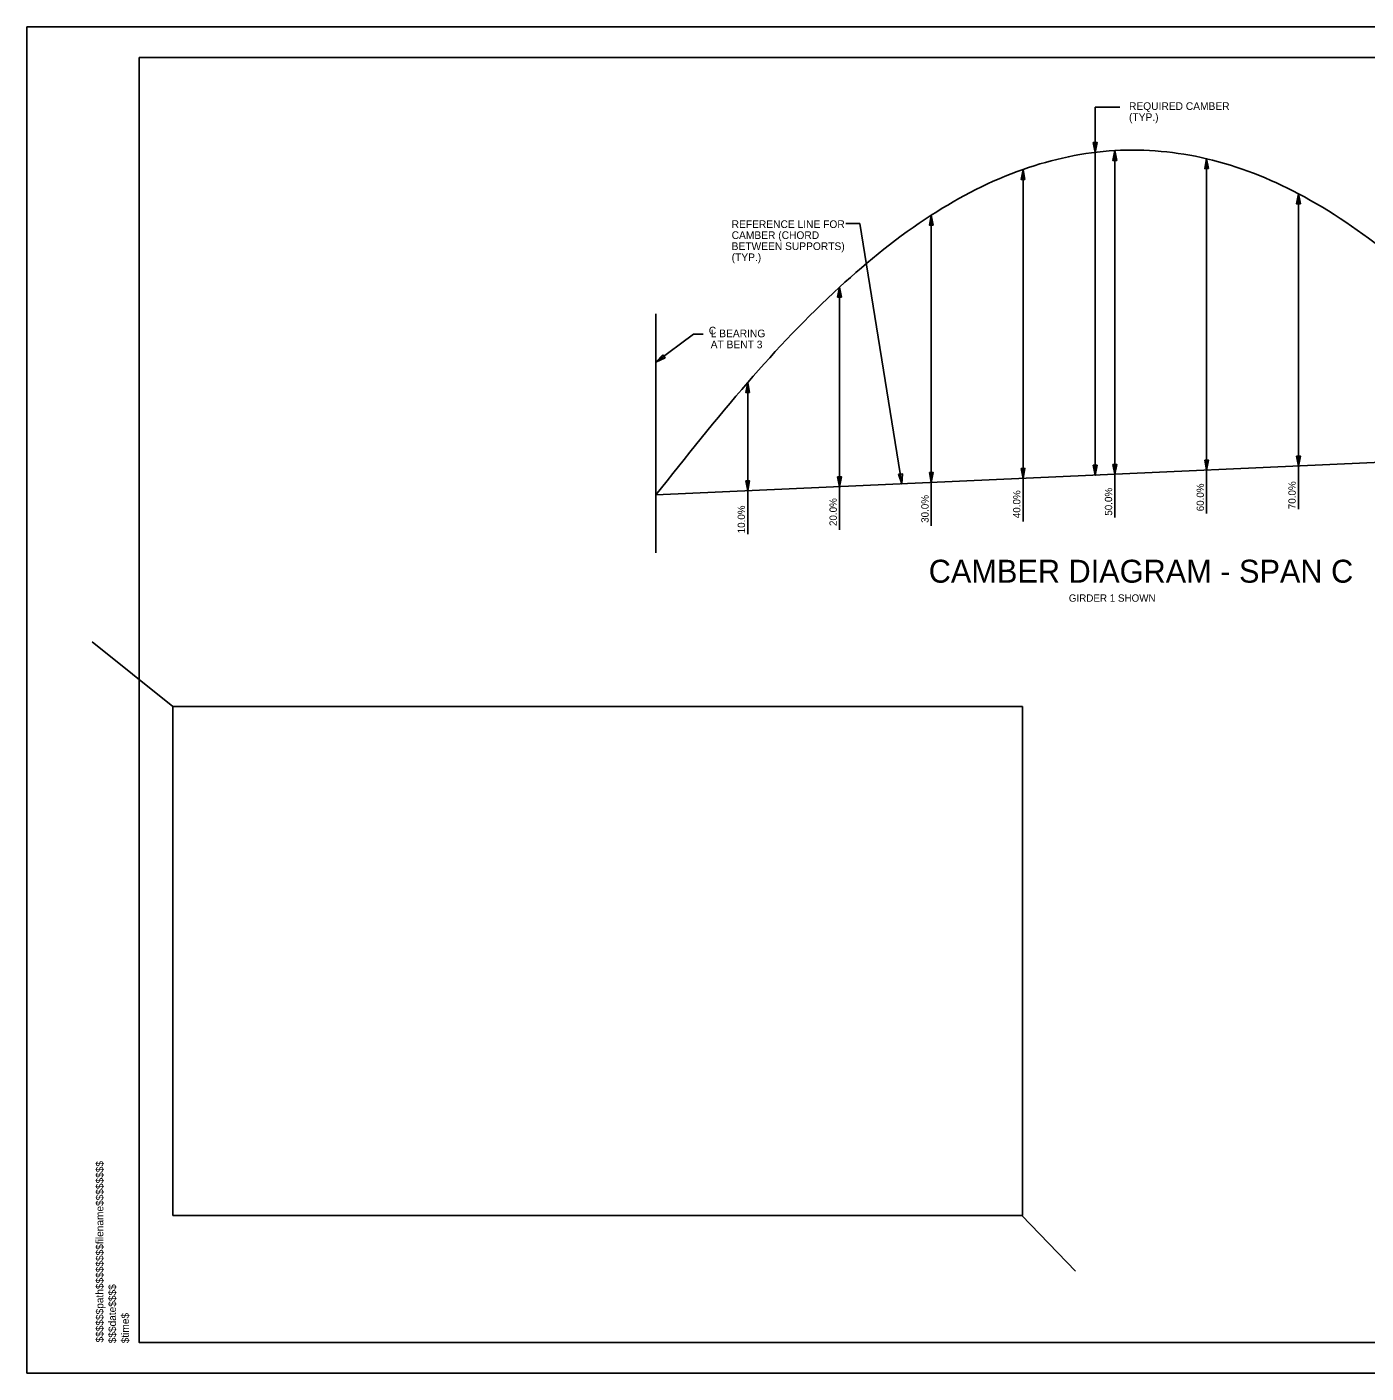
# Model space of a CAD drawing. Extents: x -125.5 to -89.4, y -5.1 to 16.9.
# Drawn here: x -125.53 to -103.65, y -5.07 to 16.93 of the extents above; entities that cross this region are included whole.
import ezdxf

# ---------------------------------------------------------------- set-up
doc = ezdxf.new("R2010")
doc.units = 0
for name, color, linetype in [('BR_AUTO DIMENSION', 7, 'Continuous'), ('BR_BORDER LINES', 7, 'Continuous'), ('BR_CENTER LINES', 7, 'Continuous'), ('BR_TABLE LINES', 7, 'Continuous'), ('BR_TEXT', 7, 'Continuous'), ('Level 31', 7, 'Continuous'), ('RD_SHT_ID', 7, 'Continuous')]:
    doc.layers.add(name, color=color, linetype=linetype)

msp = doc.modelspace()

# ---------------------------------------------------------------- linework, layer by layer
at = {"layer": 'BR_AUTO DIMENSION'}
for p, q in [((-108.075, 9.608), (-108.075, 15.622)), ((-108.075, 15.622), (-107.673, 15.622)), ((-112.149, 13.721), (-111.919, 13.721)), ((-111.919, 13.721), (-111.236, 9.466)), ((-114.641, 11.915), (-115.253, 11.456)), ((-114.481, 11.915), (-114.641, 11.915))]:
    msp.add_line(p, q, dxfattribs=at)
for points in [[(-108.106, 15.046), (-108.075, 14.884), (-108.043, 15.046)], [(-107.722, 14.75), (-107.753, 14.913), (-107.785, 14.75)], [(-106.222, 14.618), (-106.253, 14.78), (-106.285, 14.618)], [(-109.222, 14.443), (-109.253, 14.605), (-109.285, 14.443)], [(-104.722, 14.045), (-104.753, 14.208), (-104.785, 14.045)], [(-110.722, 13.695), (-110.753, 13.858), (-110.785, 13.695)], [(-112.222, 12.518), (-112.253, 12.68), (-112.285, 12.518)], [(-115.141, 11.577), (-115.253, 11.456), (-115.104, 11.527)], [(-113.722, 10.96), (-113.753, 11.123), (-113.785, 10.96)], [(-104.785, 9.92), (-104.753, 9.758), (-104.722, 9.92)], [(-109.285, 9.718), (-109.253, 9.555), (-109.222, 9.718)], [(-108.106, 9.771), (-108.075, 9.608), (-108.043, 9.771)], [(-107.785, 9.785), (-107.753, 9.623), (-107.722, 9.785)], [(-106.285, 9.853), (-106.253, 9.69), (-106.222, 9.853)], [(-113.785, 9.515), (-113.753, 9.353), (-113.722, 9.515)], [(-112.285, 9.583), (-112.253, 9.42), (-112.222, 9.583)], [(-111.288, 9.623), (-111.236, 9.466), (-111.226, 9.631)], [(-110.785, 9.65), (-110.753, 9.488), (-110.722, 9.65)]]:
    msp.add_lwpolyline(points, close=True, dxfattribs=at)
at = {"layer": 'BR_BORDER LINES'}
for p, q in [((-90.033, 16.434), (-123.699, 16.434)), ((-123.699, -4.566), (-123.699, 16.434)), ((-123.699, -4.566), (-90.033, -4.566))]:
    msp.add_line(p, q, dxfattribs=at)
at = {"layer": 'BR_CENTER LINES'}
msp.add_line((-115.253, 8.34), (-115.253, 12.247), dxfattribs=at)
at = {"layer": 'BR_TABLE LINES'}
for p, q in [((-107.753, 8.916), (-107.753, 14.913)), ((-106.253, 8.984), (-106.253, 14.78)), ((-109.253, 8.849), (-109.253, 14.605)), ((-104.753, 9.051), (-104.753, 14.208)), ((-110.753, 8.781), (-110.753, 13.858)), ((-112.253, 8.714), (-112.253, 12.68)), ((-113.753, 8.646), (-113.753, 11.123)), ((-100.257, 9.96), (-115.253, 9.285))]:
    msp.add_line(p, q, dxfattribs=at)
msp.add_lwpolyline([(-123.699, 16.434), (-90.033, 16.434), (-90.033, -4.566), (-123.699, -4.566)], close=True, dxfattribs=at)
msp.add_spline([(-115.253, 9.285), (-113.753, 11.123), (-112.253, 12.68), (-110.753, 13.858), (-109.253, 14.605), (-107.753, 14.913), (-106.253, 14.78), (-104.753, 14.208), (-103.253, 13.205), (-101.753, 11.793), (-100.257, 9.96)], degree=3, dxfattribs=at)
at = {"layer": 'Level 31'}
for p, q in [((-89.533, 16.934), (-125.533, 16.934)), ((-123.148, 5.826), (-124.469, 6.887)), ((-109.276, -2.489), (-108.399, -3.398))]:
    msp.add_line(p, q, dxfattribs=at)
msp.add_lwpolyline([(-125.533, 16.934), (-125.533, -5.066), (-89.533, -5.066), (-89.533, 16.934)], dxfattribs=at)
msp.add_lwpolyline([(-123.148, -2.489), (-109.263, -2.489), (-109.263, 5.826), (-123.148, 5.826)], close=True, dxfattribs=at)

# ---------------------------------------------------------------- texts
at = {"layer": 'BR_AUTO DIMENSION'}
for s, p in [('REQUIRED CAMBER', (-107.522, 15.577)), ('(TYP.)', (-107.522, 15.397)), ('REFERENCE LINE FOR', (-114.016, 13.648)), ('CAMBER (CHORD', (-114.016, 13.468)), ('(TYP.)', (-114.016, 13.107)), ('BETWEEN SUPPORTS)', (-114.016, 13.288)), ('C', (-114.389, 11.909)), ('L BEARING', (-114.358, 11.862)), ('AT BENT 3', (-114.358, 11.682))]:
    msp.add_text(s, height=0.125, dxfattribs=at).set_placement(p)
at = {"layer": 'BR_TEXT'}
for s, p in [('60.0%', (-106.297, 9.018)), ('70.0%', (-104.797, 9.052)), ('30.0%', (-110.797, 8.829)), ('40.0%', (-109.297, 8.905)), ('50.0%', (-107.797, 8.946)), ('10.0%', (-113.797, 8.658)), ('20.0%', (-112.297, 8.777))]:
    msp.add_text(s, height=0.12, rotation=90, dxfattribs=at).set_placement(p)
for s, height, p in [('CAMBER DIAGRAM - SPAN C', 0.375, (-110.795, 7.851)), ('GIRDER 1 SHOWN', 0.12, (-108.505, 7.54))]:
    msp.add_text(s, height=height, dxfattribs=at).set_placement(p)
at = {"layer": 'RD_SHT_ID'}
for s, height, p in [('$$$$$$path$$$$$$$$filename$$$$$$$$', 0.12347, (-124.283, -4.566)), ('$$$date$$$$', 0.12347, (-124.077, -4.579)), ('$time$', 0.1235, (-123.866, -4.579))]:
    msp.add_text(s, height=height, rotation=90, dxfattribs=at).set_placement(p)

doc.saveas('drawing.dxf')
